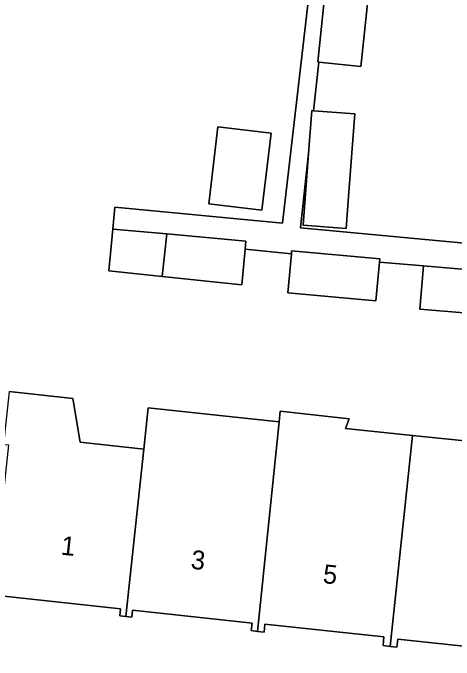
# Model space of a CAD drawing. Extents: x 162396 to 163643, y 386452 to 387406.
# Drawn here: x 162555.08 to 162578.45, y 386566.47 to 386600.76 of the extents above; entities that cross this region are included whole.
import ezdxf

# ---------------------------------------------------------------- set-up
doc = ezdxf.new("R2010")
doc.units = 0
for name, color, linetype in [('IMGEO_Erf', 7, 'Continuous'), ('IMGEO_Pand', 7, 'Continuous'), ('IMGEO_Pand_nummerreeks', 7, 'Continuous'), ('IMGEO_Voetpad_open', 7, 'Continuous')]:
    doc.layers.add(name, color=color, linetype=linetype)

msp = doc.modelspace()

# ---------------------------------------------------------------- linework, layer by layer
at = {"layer": 'IMGEO_Erf'}
for points in [[(162596.17, 386613.523), (162573.621, 386621.455), (162572.865, 386612.427), (162575.967, 386612.081), (162575.162, 386604.868), (162572.06, 386605.214), (162571.791, 386602.773), (162574.014, 386602.603), (162573.55, 386598.243), (162573.516, 386597.92), (162571.284, 386598.158), (162571, 386595.578), (162573.194, 386595.411), (162572.861, 386591.042), (162572.731, 386589.343), (162570.462, 386589.516), (162570.75, 386593.304), (162570.318, 386589.379), (162593.535, 386587.193), (162595.004, 386587.03), (162597.635, 386611.189)], [(162581.084, 386584.694), (162576.633, 386585.071), (162576.827, 386587.354), (162574.5, 386587.551), (162574.314, 386585.497), (162569.645, 386585.921), (162569.833, 386587.992), (162567.381, 386588.249), (162567.208, 386586.345), (162565.686, 386586.508), (162562.995, 386586.797), (162560.173, 386587.1), (162560.375, 386589.31), (162560.49, 386590.47), (162569.356, 386589.617), (162571.116, 386604.713)], [(162554.892, 386580.7), (162558.266, 386580.338), (162558.653, 386578.011), (162562.013, 386577.65), (162562.248, 386579.842), (162565.875, 386579.452), (162569.185, 386579.096), (162569.242, 386579.652), (162572.893, 386579.246), (162572.7, 386578.743), (162576.254, 386578.363), (162579.886, 386578)], [(162581.623, 386566.921), (162575.474, 386567.581), (162575.428, 386567.159), (162575.06, 386567.198), (162574.69, 386567.238), (162574.74, 386567.702), (162568.432, 386568.38), (162568.387, 386567.957), (162568.048, 386567.993), (162567.71, 386568.029), (162567.753, 386568.425), (162561.415, 386569.106), (162561.377, 386568.745), (162561.06, 386568.779), (162560.744, 386568.813), (162560.784, 386569.187), (162554.449, 386569.868)]]:
    msp.add_lwpolyline(points, dxfattribs=at)
msp.add_lwpolyline([(162565.944, 386594.73), (162568.758, 386594.394), (162568.27, 386590.312), (162565.457, 386590.648)], close=True, dxfattribs=at)
at = {"layer": 'IMGEO_Pand'}
for points in [[(162571.791, 386602.773), (162571.722, 386602.778), (162571.231, 386598.164), (162571.284, 386598.158), (162573.516, 386597.92), (162573.55, 386598.243), (162574.014, 386602.603)], [(162571, 386595.578), (162570.924, 386595.584), (162570.75, 386593.304), (162570.462, 386589.516), (162572.731, 386589.343), (162572.861, 386591.042), (162573.194, 386595.411)], [(162565.457, 386590.648), (162568.27, 386590.312), (162568.758, 386594.394), (162565.944, 386594.73)], [(162563.238, 386589.05), (162560.375, 386589.31), (162560.173, 386587.1), (162562.995, 386586.797)], [(162567.381, 386588.249), (162567.419, 386588.67), (162563.238, 386589.05), (162562.995, 386586.797), (162565.686, 386586.508), (162567.208, 386586.345)], [(162574.5, 386587.551), (162574.516, 386587.726), (162569.847, 386588.151), (162569.833, 386587.992), (162569.645, 386585.921), (162574.314, 386585.497)], [(162576.827, 386587.354), (162576.633, 386585.071), (162581.084, 386584.694), (162581.251, 386586.674), (162581.277, 386586.977)], [(162562.013, 386577.65), (162558.653, 386578.011), (162558.266, 386580.338), (162554.892, 386580.7), (162554.591, 386577.897), (162554.842, 386577.87), (162553.944, 386569.512), (162554.405, 386569.462), (162554.449, 386569.868), (162560.784, 386569.187), (162560.744, 386568.813), (162561.06, 386568.779)], [(162565.875, 386579.452), (162562.248, 386579.842), (162562.013, 386577.65), (162561.06, 386568.779), (162561.377, 386568.745), (162561.415, 386569.106), (162567.753, 386568.425), (162567.71, 386568.029), (162568.048, 386567.993), (162569.185, 386579.096)], [(162576.025, 386576.198), (162576.254, 386578.363), (162572.7, 386578.743), (162572.893, 386579.246), (162569.242, 386579.652), (162569.185, 386579.096), (162568.048, 386567.993), (162568.387, 386567.957), (162568.432, 386568.38), (162574.74, 386567.702), (162574.69, 386567.238), (162575.06, 386567.198)], [(162579.886, 386578), (162576.254, 386578.363), (162576.025, 386576.198), (162575.06, 386567.198), (162575.428, 386567.159), (162575.474, 386567.581), (162581.623, 386566.921), (162581.578, 386566.508), (162581.92, 386566.471), (162583.082, 386577.656)]]:
    msp.add_lwpolyline(points, close=True, dxfattribs=at)
at = {"layer": 'IMGEO_Voetpad_open'}
for points in [[(162571.116, 386604.713), (162569.356, 386589.617), (162560.49, 386590.47), (162560.375, 386589.31), (162563.238, 386589.05), (162567.419, 386588.67), (162567.381, 386588.249), (162569.833, 386587.992), (162569.847, 386588.151), (162574.516, 386587.726), (162574.5, 386587.551), (162576.827, 386587.354), (162581.277, 386586.977)], [(162593.535, 386587.193), (162570.318, 386589.379), (162570.75, 386593.304), (162570.924, 386595.584), (162571, 386595.578), (162571.284, 386598.158), (162571.231, 386598.164), (162571.722, 386602.778)]]:
    msp.add_lwpolyline(points, dxfattribs=at)

# ---------------------------------------------------------------- texts
at = {"layer": 'IMGEO_Pand_nummerreeks'}
for s, rotation, p in [('1', 353.8105, (162557.595, 386572.062)), ('3', 353.8105, (162564.476, 386571.315)), ('5', 353.8121, (162571.472, 386570.557))]:
    msp.add_text(s, height=1, rotation=rotation, dxfattribs=at).set_placement(p)

doc.saveas('drawing.dxf')
